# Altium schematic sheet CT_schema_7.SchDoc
size 278 x 170 mm
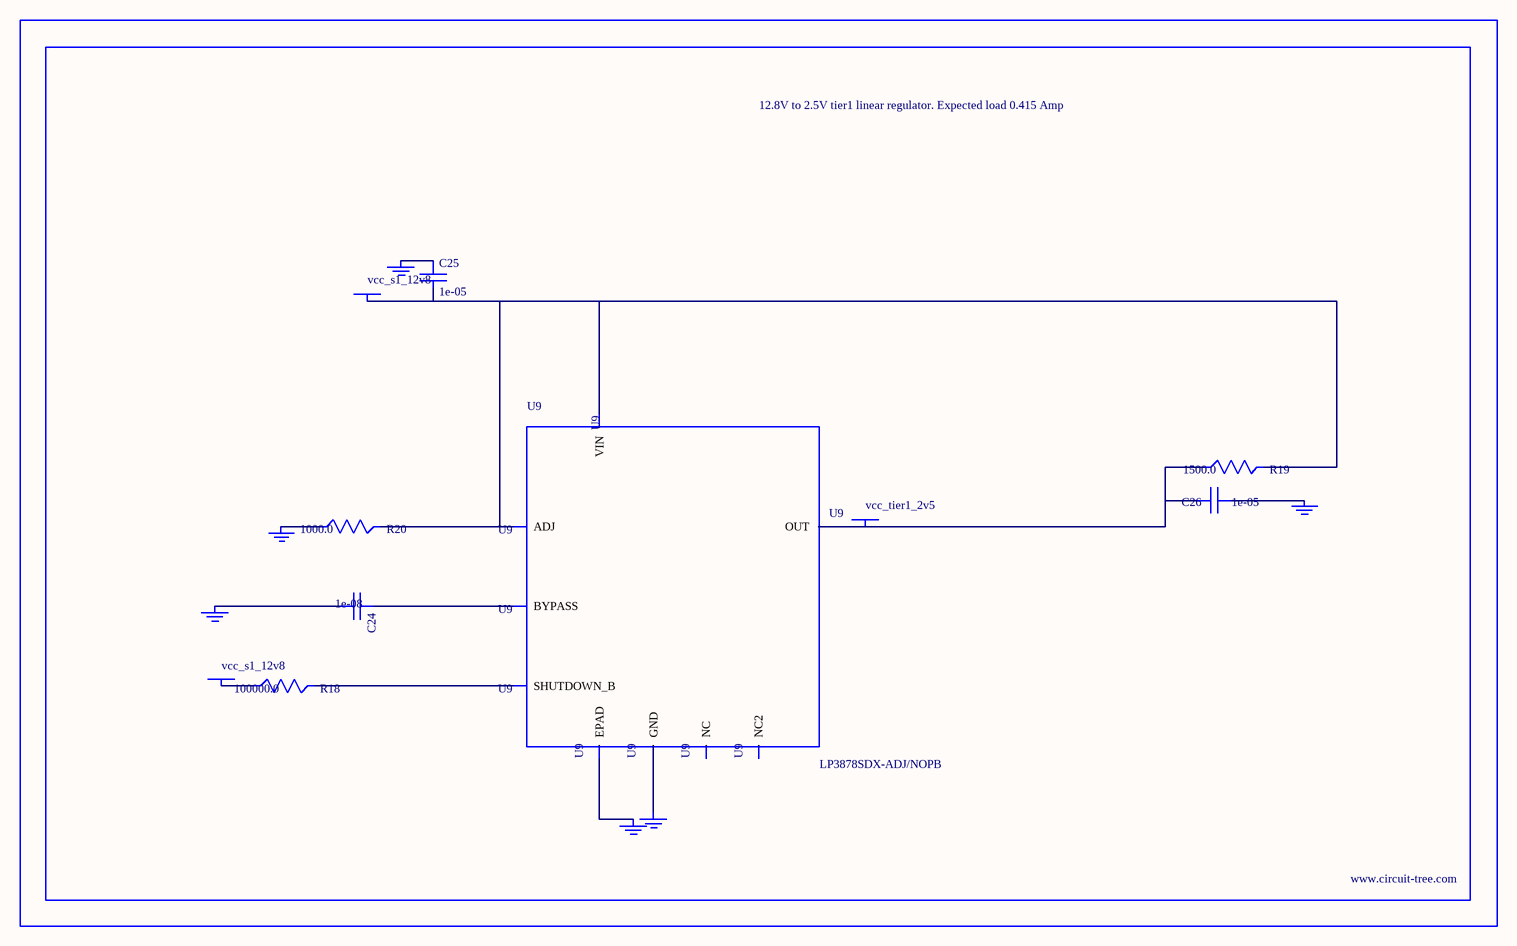
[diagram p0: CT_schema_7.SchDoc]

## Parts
BORDER6  (no value)
C24  1e-08  [C0402]
C25  1e-05  [C1210]
C26  1e-05  [C1210]
GND_INSTANCE_6_0  (no value)
GND_INSTANCE_6_1  (no value)
GND_INSTANCE_6_2  (no value)
GND_INSTANCE_6_3  (no value)
GND_INSTANCE_6_4  (no value)
GND_INSTANCE_6_5  (no value)
POWER_INSTANCE_6_0  vcc_s1_12v8
POWER_INSTANCE_6_1  vcc_s1_12v8
POWER_INSTANCE_6_2  vcc_tier1_2v5
R18  100000.0  [R0603]
R19  1500.0  [R0603]
R20  1000.0  [R0603]
U9  LP3878SDX-ADJ/NOPB  [WSON-8]

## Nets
NetC24_1: C24.1 U9.1(BYPASS)
NetC24_2: C24.2 GND_INSTANCE_6_0.0(GND)
NetC25_1: C25.1 GND_INSTANCE_6_1.0(GND)
NetC25_2: C25.2 POWER_INSTANCE_6_0.0(PWR) R19.2 R20.2 U9.4(VIN) U9.6(ADJ)
NetC26_1: C26.1 GND_INSTANCE_6_2.0(GND)
NetC26_2: C26.2 POWER_INSTANCE_6_2.0(PWR) R19.1 U9.5(OUT)
NetGND_INSTANCE_6_3_0: GND_INSTANCE_6_3.0(GND) R20.1
NetGND_INSTANCE_6_4_0: GND_INSTANCE_6_4.0(GND) U9.PAD(EPAD)
NetGND_INSTANCE_6_5_0: GND_INSTANCE_6_5.0(GND) U9.3(GND)
NetPOWER_INSTANCE_6_1_0: POWER_INSTANCE_6_1.0(PWR) R18.1
NetR18_2: R18.2 U9.8(SHUTDOWN_B)

Not connected (* = marked no-connect by the designer): U9 2(NC) 7(NC2)

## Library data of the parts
BORDER6 = BORDER_PAGE6
C24 = C0402C103K3RAC
C25 = C1210C106K5PACTU
C26 = GRM32DR61E106MA12L
GND_INSTANCE_6_0-GND_INSTANCE_6_5 = GND
POWER_INSTANCE_6_0-POWER_INSTANCE_6_2 = PWR
R18 = RC0603JR-07100KL
R19 = RC0603JR-071K5L
R20 = RC0603JR-071KL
